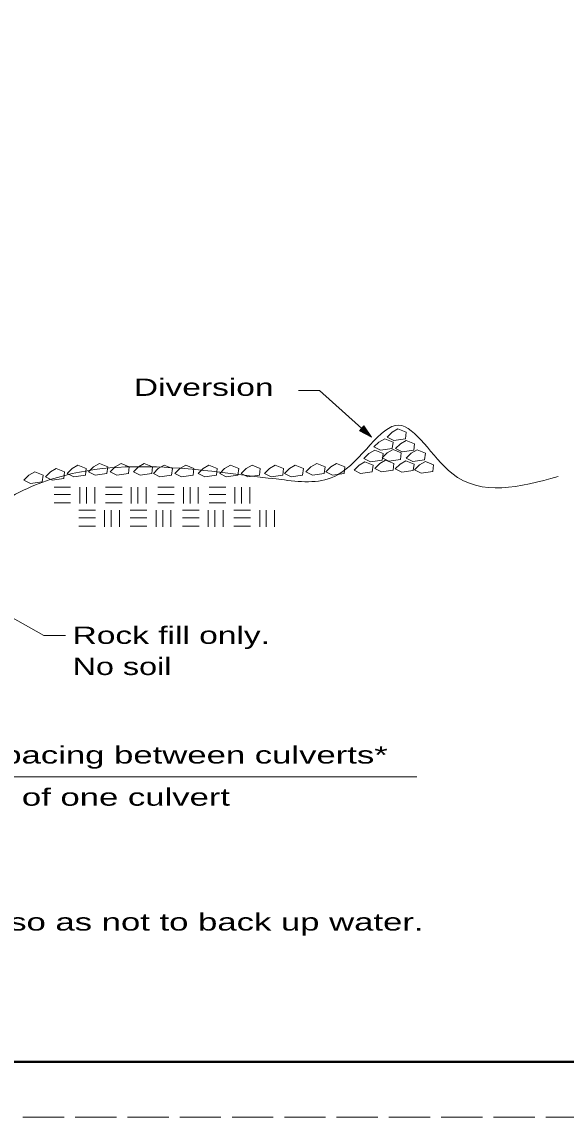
# Model space of a CAD drawing. Extents: x 1083.1 to 1117.1, y 719.4 to 741.4.
# Drawn here: x 1099.17 to 1104.08, y 719.35 to 729.24 of the extents above; entities that cross this region are included whole.
import ezdxf

# ---------------------------------------------------------------- set-up
doc = ezdxf.new("R2010")
doc.units = 0
doc.header["$LTSCALE"] = 0.062
doc.linetypes.add('LONG_DASHED', pattern=[7.5, 6, -1.5])
doc.layers.add('1', color=7, linetype='Continuous', lineweight=13)

msp = doc.modelspace()

# ---------------------------------------------------------------- hatches: boundary and pattern name
at = {"layer": '1'}
msp.add_hatch(color=256, dxfattribs=at).paths.add_polyline_path([(1102.21283, 725.54733), (1102.32, 725.49083), (1102.25208, 725.59108)])

# ---------------------------------------------------------------- linework, layer by layer
for p, q in [((1099.45558, 725.03933), (1099.60525, 725.03933)), ((1099.68767, 724.88958), (1099.68767, 725.03925)), ((1099.7475, 724.88958), (1099.7475, 725.03925)), ((1099.82233, 724.88958), (1099.82233, 725.03925)), ((1099.91967, 725.03933), (1100.06933, 725.03933)), ((1100.15175, 724.88958), (1100.15175, 725.03925)), ((1100.21158, 724.88958), (1100.21158, 725.03925)), ((1100.28642, 724.88958), (1100.28642, 725.03925)), ((1100.39117, 725.03933), (1100.54083, 725.03933)), ((1100.62325, 724.88958), (1100.62325, 725.03925)), ((1100.68308, 724.88958), (1100.68308, 725.03925)), ((1100.75792, 724.88958), (1100.75792, 725.03925)), ((1100.85525, 725.03933), (1101.00492, 725.03933)), ((1101.08733, 724.88958), (1101.08733, 725.03925)), ((1101.14717, 724.88958), (1101.14717, 725.03925)), ((1101.222, 724.88958), (1101.222, 725.03925)), ((1099.45558, 724.97192), (1099.60525, 724.97192)), ((1099.91967, 724.97192), (1100.06933, 724.97192)), ((1100.39117, 724.97192), (1100.54083, 724.97192)), ((1100.85525, 724.97192), (1101.00492, 724.97192)), ((1099.45558, 724.897), (1099.60525, 724.897)), ((1099.68008, 724.82967), (1099.82975, 724.82967)), ((1099.91217, 724.67992), (1099.91217, 724.82958)), ((1099.91967, 724.897), (1100.06933, 724.897)), ((1099.972, 724.67992), (1099.972, 724.82958)), ((1100.04683, 724.67992), (1100.04683, 724.82958)), ((1100.14417, 724.82967), (1100.29383, 724.82967)), ((1100.37625, 724.67992), (1100.37625, 724.82958)), ((1100.39117, 724.897), (1100.54083, 724.897)), ((1100.43608, 724.67992), (1100.43608, 724.82958)), ((1100.51092, 724.67992), (1100.51092, 724.82958)), ((1100.61567, 724.82967), (1100.76533, 724.82967)), ((1100.84775, 724.67992), (1100.84775, 724.82958)), ((1100.85525, 724.897), (1101.00492, 724.897)), ((1100.90758, 724.67992), (1100.90758, 724.82958)), ((1100.98242, 724.67992), (1100.98242, 724.82958)), ((1101.07975, 724.82967), (1101.22942, 724.82967)), ((1101.31183, 724.67992), (1101.31183, 724.82958)), ((1101.37167, 724.67992), (1101.37167, 724.82958)), ((1101.4465, 724.67992), (1101.4465, 724.82958)), ((1099.68008, 724.76225), (1099.82975, 724.76225)), ((1100.14417, 724.76225), (1100.29383, 724.76225)), ((1100.61567, 724.76225), (1100.76533, 724.76225)), ((1101.07975, 724.76225), (1101.22942, 724.76225)), ((1099.68008, 724.68733), (1099.82975, 724.68733)), ((1100.14417, 724.68733), (1100.29383, 724.68733)), ((1100.61567, 724.68733), (1100.76533, 724.68733)), ((1101.07975, 724.68733), (1101.22942, 724.68733)), ((1096.65492, 722.42458), (1102.73067, 722.42458))]:
    msp.add_line(p, q, dxfattribs=at)
at = {"layer": '1', "linetype": 'LONG_DASHED'}
msp.add_lwpolyline([(1083.12642, 719.35408), (1117.12642, 719.35408), (1117.12642, 741.35408), (1083.12642, 741.35408)], close=True, dxfattribs=at)
at = {"layer": '1', "lineweight": 25}
msp.add_lwpolyline([(1116.62642, 719.85408), (1085.12642, 719.85408), (1085.12642, 740.85408)], dxfattribs=at)
at = {"layer": '1', "lineweight": 40}
for points in [[(1116.62642, 719.85408), (1085.12642, 719.85408), (1085.12642, 740.85408), (1116.62642, 740.85408)], [(1116.62642, 719.85408), (1085.12642, 719.85408), (1085.12642, 740.85408)]]:
    msp.add_lwpolyline(points, dxfattribs=at)
at = {"layer": '1'}
for points in [[(1102.32, 725.49083), (1101.85183, 725.90992), (1101.66292, 725.90992)], [(1098.40208, 724.24192), (1099.36308, 723.69958), (1099.56025, 723.69958)]]:
    msp.add_lwpolyline(points, dxfattribs=at)
for points in [[(1102.21283, 725.54733), (1102.32, 725.49083), (1102.25208, 725.59108)], [(1102.56008, 725.56575), (1102.50767, 725.53575), (1102.46275, 725.49083), (1102.52258, 725.46092), (1102.62742, 725.47592), (1102.63492, 725.53575)], [(1102.44033, 725.47592), (1102.38792, 725.44592), (1102.343, 725.401), (1102.40283, 725.37108), (1102.50767, 725.38608), (1102.51517, 725.44592)], [(1102.63492, 725.46092), (1102.5825, 725.43092), (1102.53758, 725.386), (1102.59742, 725.35608), (1102.70225, 725.37108), (1102.70975, 725.43092)], [(1102.3505, 725.37108), (1102.29808, 725.34108), (1102.25317, 725.29617), (1102.313, 725.26625), (1102.41783, 725.28125), (1102.42533, 725.34108)], [(1102.51525, 725.37867), (1102.46283, 725.34867), (1102.41792, 725.30375), (1102.47775, 725.27383), (1102.58258, 725.28883), (1102.59008, 725.34867)], [(1102.73225, 725.37483), (1102.67983, 725.34483), (1102.63492, 725.29992), (1102.69475, 725.27), (1102.79958, 725.285), (1102.80708, 725.34483)], [(1099.47625, 725.20633), (1099.42383, 725.17633), (1099.37892, 725.13142), (1099.43875, 725.1015), (1099.54358, 725.1165), (1099.55108, 725.17633)], [(1099.67083, 725.23633), (1099.61842, 725.20633), (1099.5735, 725.16142), (1099.63333, 725.1315), (1099.73817, 725.1465), (1099.74567, 725.20633)], [(1099.86542, 725.25125), (1099.813, 725.22125), (1099.76808, 725.17633), (1099.82792, 725.14642), (1099.93275, 725.16142), (1099.94025, 725.22125)], [(1100.06008, 725.25125), (1100.00767, 725.22125), (1099.96275, 725.17633), (1100.02258, 725.14642), (1100.12742, 725.16142), (1100.13492, 725.22125)], [(1100.26967, 725.25125), (1100.21725, 725.22125), (1100.17233, 725.17633), (1100.23217, 725.14642), (1100.337, 725.16142), (1100.3445, 725.22125)], [(1100.44925, 725.23633), (1100.39683, 725.20633), (1100.35192, 725.16142), (1100.41175, 725.1315), (1100.51658, 725.1465), (1100.52408, 725.20633)], [(1100.64392, 725.23633), (1100.5915, 725.20633), (1100.54658, 725.16142), (1100.60642, 725.1315), (1100.71125, 725.1465), (1100.71875, 725.20633)], [(1100.8535, 725.23633), (1100.80108, 725.20633), (1100.75617, 725.16142), (1100.816, 725.1315), (1100.92083, 725.1465), (1100.92833, 725.20633)], [(1101.04808, 725.23633), (1100.99567, 725.20633), (1100.95075, 725.16142), (1101.01058, 725.1315), (1101.11542, 725.1465), (1101.12292, 725.20633)], [(1101.24267, 725.23633), (1101.19025, 725.20633), (1101.14533, 725.16142), (1101.20517, 725.1315), (1101.31, 725.1465), (1101.3175, 725.20633)], [(1101.45225, 725.23633), (1101.39983, 725.20633), (1101.35492, 725.16142), (1101.41475, 725.1315), (1101.51958, 725.1465), (1101.52708, 725.20633)], [(1101.63192, 725.23633), (1101.5795, 725.20633), (1101.53458, 725.16142), (1101.59442, 725.1315), (1101.69925, 725.1465), (1101.70675, 725.20633)], [(1101.8265, 725.25125), (1101.77408, 725.22125), (1101.72917, 725.17633), (1101.789, 725.14642), (1101.89383, 725.16142), (1101.90133, 725.22125)], [(1102.00617, 725.25125), (1101.95375, 725.22125), (1101.90883, 725.17633), (1101.96867, 725.14642), (1102.0735, 725.16142), (1102.081, 725.22125)], [(1102.26067, 725.26625), (1102.20825, 725.23625), (1102.16333, 725.19133), (1102.22317, 725.16142), (1102.328, 725.17642), (1102.3355, 725.23625)], [(1102.44783, 725.28117), (1102.39542, 725.25117), (1102.3505, 725.20625), (1102.41033, 725.17633), (1102.51517, 725.19133), (1102.52267, 725.25117)], [(1102.63117, 725.2775), (1102.57875, 725.2475), (1102.53383, 725.20258), (1102.59367, 725.17267), (1102.6985, 725.18767), (1102.706, 725.2475)], [(1102.80708, 725.27), (1102.75467, 725.24), (1102.70975, 725.19508), (1102.76958, 725.16517), (1102.87442, 725.18017), (1102.88192, 725.24)], [(1099.28158, 725.17642), (1099.22917, 725.14642), (1099.18425, 725.1015), (1099.24408, 725.07158), (1099.34892, 725.08658), (1099.35642, 725.14642)]]:
    msp.add_lwpolyline(points, close=True, dxfattribs=at)
msp.add_spline([(1087.80692, 725.11858), (1089.39375, 725.11858), (1089.96258, 725.463), (1090.33683, 725.1485), (1091.66917, 725.10358), (1092.268, 724.99875), (1092.77692, 724.63933), (1093.19608, 724.14517), (1093.89967, 723.77075), (1097.64217, 723.80075), (1097.732, 723.80075), (1098.37575, 724.30992), (1098.75, 724.72925), (1099.28892, 725.05867), (1101.53442, 725.10358), (1102.01342, 725.1485), (1102.56733, 725.59783), (1103.04642, 725.1635), (1104.0045, 725.13358)], degree=3, dxfattribs=at)

# ---------------------------------------------------------------- texts
for s, width, p in [('Diversion', 1.45, (1100.17625, 725.86242)), ('Rock fill only.', 1.45, (1099.62267, 723.62433)), ('No soil', 1.4, (1099.62267, 723.34333)), ("10' Maximum spacing between culverts*", 1.5, (1096.8945, 722.54442)), ('with a minimum of one culvert', 1.5, (1096.90517, 722.16408)), ('*Place culverts so as not to back up water.', 1.5, (1096.8945, 721.03725))]:
    msp.add_text(s, height=0.156, dxfattribs=dict(at, width=width)).set_placement(p)

doc.saveas('drawing.dxf')
